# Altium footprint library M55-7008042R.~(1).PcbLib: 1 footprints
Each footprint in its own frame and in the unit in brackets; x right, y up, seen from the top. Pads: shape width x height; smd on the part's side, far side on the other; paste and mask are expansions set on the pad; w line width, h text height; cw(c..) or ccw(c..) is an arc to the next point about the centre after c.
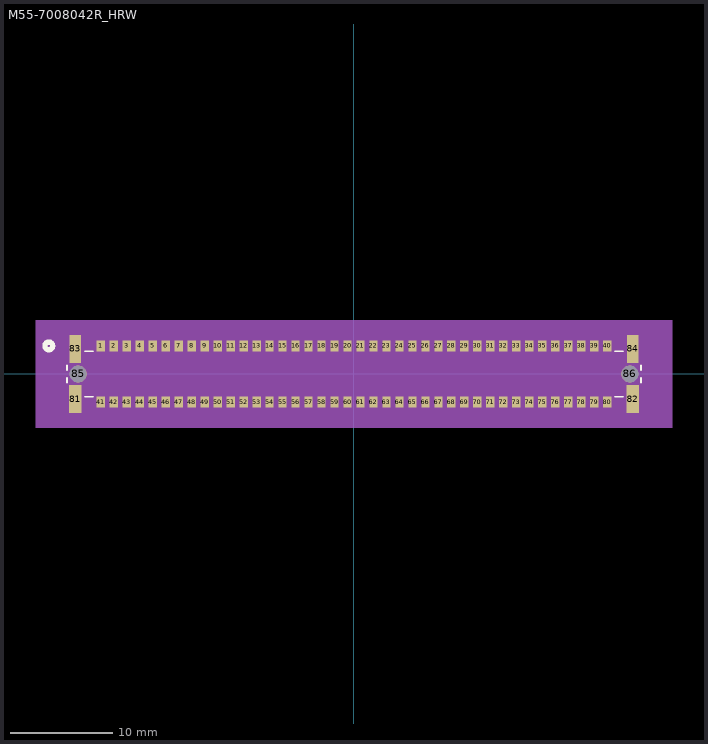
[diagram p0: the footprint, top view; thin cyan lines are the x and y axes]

## M55-7008042R_HRW [mil]
pads (86):
  rect 32x43 smd paste+0 mask+0: 1(-975,108.27) 2(-925,108.27) 3(-875,108.27) 4(-825,108.27) 5(-775,108.27) 6(-725,108.27) 7(-675,108.27) 8(-625,108.27) 9(-575,108.27) 10(-525,108.27) 11(-475,108.27) 12(-425,108.27) 13(-375,108.27) 14(-325,108.27) 15(-275,108.27) 16(-225,108.27) 17(-175,108.27) 18(-125,108.27) 19(-75,108.27) 20(-25,108.27) 21(25,108.27) 22(75,108.27) 23(125,108.27) 24(175,108.27) 25(225,108.27) 26(275,108.27) 27(325,108.27) 28(375,108.27) 29(425,108.27) 30(475,108.27) 31(525,108.27) 32(575,108.27) 33(625,108.27) 34(675,108.27) 35(725,108.27) 36(775,108.27) 37(825,108.27) 38(875,108.27) 39(925,108.27) 40(975,108.27) 41(-975,-108.27) 42(-925,-108.27) 43(-875,-108.27) 44(-825,-108.27) 45(-775,-108.27) 46(-725,-108.27) 47(-675,-108.27) 48(-625,-108.27) 49(-575,-108.27) 50(-525,-108.27) 51(-475,-108.27) 52(-425,-108.27) 53(-375,-108.27) 54(-325,-108.27) 55(-275,-108.27) 56(-225,-108.27) 57(-175,-108.27) 58(-125,-108.27) 59(-75,-108.27) 60(-25,-108.27) 61(25,-108.27) 62(75,-108.27) 63(125,-108.27) 64(175,-108.27) 65(225,-108.27) 66(275,-108.27) 67(325,-108.27) 68(375,-108.27) 69(425,-108.27) 70(475,-108.27) 71(525,-108.27) 72(575,-108.27) 73(625,-108.27) 74(675,-108.27) 75(725,-108.27) 76(775,-108.27) 77(825,-108.27) 78(875,-108.27) 79(925,-108.27) 80(975,-108.27)
  rect 47x106 smd: 81(-1073.23,-96.31) 82(1073.23,-96.31)
  rect 46x106 smd: 83(-1073.23,96.31) 84(1073.23,96.31)
  round 65 hole 65 unplated: 85(-1062.01,0) 86(1062.01,0)
Top Overlay:
  circle w20: c-1175,108.27 r15
  lines w6: -1105,-33.15 -1105,-15.2 ; -1105,15.2 -1105,33.57 ; -1037.13,87.5 -1004.1,87.5 ; -1036.63,-87.5 -1004.1,-87.5 ; 1004.1,-87.5 1036.63,-87.5 ; 1004.1,87.5 1037.13,87.5 ; 1105,-33.15 1105,-15.2 ; 1105,15.2 1105,33.57
Bottom Overlay:
  circle w20: c-1175,108.27 r15
Mechanical 5:
  region: -1225,207.5 1225,207.5 1225,-207.5 -1225,-207.5
Mechanical 13:
  circle w20: c-975,183.27 r15
  lines w1: -1100,-82.5 1100,-82.5 1100,82.5 -1100,82.5 -1100,-82.5
Mechanical 15:
  region: 1136.23,139.77 -1136.23,139.77 -1136.23,-139.77 1136.23,-139.77
  lines w6: -1136.23,-139.77 -1136.23,139.77 1136.23,139.77 1136.23,-139.77 -1136.23,-139.77
3D body: height 10, standoff 0, extent 0,0 10,10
